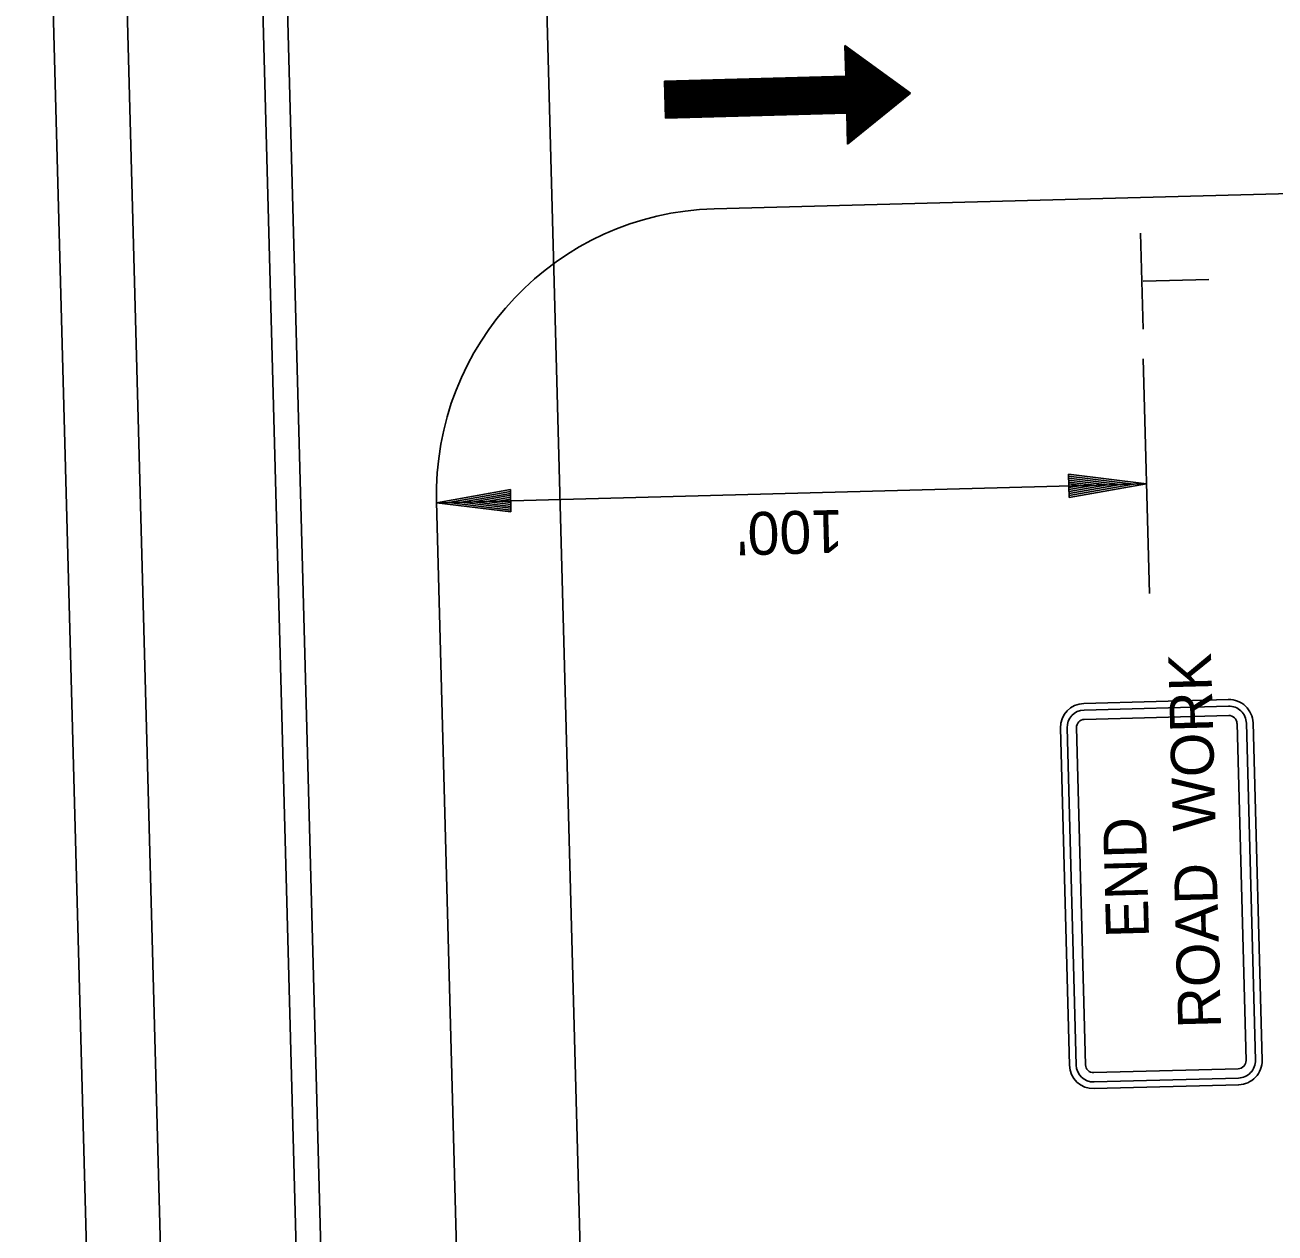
# Model space of a CAD drawing. Extents: x 1929653 to 1931621, y 596452 to 600944.
# Drawn here: x 1930900.9 to 1931163.6, y 597788.5 to 598042.4 of the extents above; entities that cross this region are included whole.
import ezdxf

# ---------------------------------------------------------------- set-up
doc = ezdxf.new("R2010")
doc.units = 0
for name, color, linetype in [('P_TC_Signs_Temporary', 7, 'Continuous'), ('R_Border', 7, 'Continuous'), ('R_Draft', 7, 'Continuous')]:
    doc.layers.add(name, color=color, linetype=linetype)

msp = doc.modelspace()

# ---------------------------------------------------------------- linework, layer by layer
at = {"layer": 'P_TC_Signs_Temporary'}
for p, q in [((1931153.84, 597900.67), (1931123.47, 597899.85)), ((1931153.87, 597899.26), (1931123.51, 597898.45)), ((1931153.93, 597897.3), (1931123.56, 597896.48)), ((1931157.56, 597824.8), (1931155.66, 597895.65)), ((1931159.53, 597824.86), (1931157.63, 597895.71)), ((1931160.93, 597824.9), (1931159.03, 597895.74)), ((1931118.55, 597894.66), (1931120.45, 597823.81)), ((1931119.95, 597894.7), (1931121.85, 597823.85)), ((1931121.92, 597894.75), (1931123.82, 597823.9)), ((1931125.55, 597822.26), (1931155.92, 597823.07)), ((1931125.61, 597820.29), (1931155.97, 597821.1)), ((1931125.65, 597818.88), (1931156.01, 597819.7))]:
    msp.add_line(p, q, dxfattribs=at)
for centre, radius, start, end in [((1931153.97, 597895.61), 5.06, 1.5377, 91.5377), ((1931123.61, 597894.79), 5.06, 91.5377, 181.5377), ((1931123.61, 597894.79), 3.66, 91.5377, 181.5377), ((1931153.97, 597895.61), 3.66, 1.5377, 91.5377), ((1931123.61, 597894.79), 1.69, 91.5377, 181.5377), ((1931153.97, 597895.61), 1.69, 1.5377, 91.5377), ((1931155.87, 597824.76), 1.69, 271.5377, 1.5377), ((1931155.87, 597824.76), 3.66, 271.5377, 1.5377), ((1931155.87, 597824.76), 5.06, 271.5377, 1.5377), ((1931125.51, 597823.94), 5.06, 181.5377, 271.5377), ((1931125.51, 597823.94), 3.66, 181.5377, 271.5377), ((1931125.51, 597823.94), 1.69, 181.5377, 271.5377)]:
    msp.add_arc(centre, radius, start, end, dxfattribs=at)
at = {"layer": 'R_Border'}
for p, q in [((1931073.28, 598038.09), (1931073.29, 598038.11)), ((1931073.28, 598037.91), (1931073.4, 598038.03)), ((1931073.29, 598037.72), (1931073.51, 598037.96)), ((1931073.29, 598037.54), (1931073.61, 598037.88)), ((1931073.3, 598037.36), (1931073.72, 598037.8)), ((1931073.3, 598037.17), (1931073.82, 598037.72)), ((1931073.31, 598036.99), (1931073.93, 598037.65)), ((1931073.31, 598036.8), (1931074.04, 598037.57)), ((1931073.32, 598036.62), (1931074.14, 598037.49)), ((1931073.32, 598036.44), (1931074.25, 598037.42)), ((1931073.33, 598036.25), (1931074.35, 598037.34)), ((1931073.33, 598036.07), (1931074.46, 598037.26)), ((1931073.34, 598035.88), (1931074.57, 598037.18)), ((1931073.34, 598035.7), (1931074.67, 598037.11)), ((1931073.34, 598035.52), (1931074.78, 598037.03)), ((1931073.35, 598035.33), (1931074.88, 598036.95)), ((1931066.05, 598023.66), (1931077.11, 598035.33)), ((1931066.23, 598023.67), (1931077.21, 598035.25)), ((1931066.42, 598023.67), (1931077.32, 598035.18)), ((1931066.6, 598023.68), (1931077.43, 598035.1)), ((1931066.78, 598023.68), (1931077.53, 598035.02)), ((1931066.97, 598023.69), (1931077.64, 598034.94)), ((1931067.15, 598023.69), (1931077.74, 598034.87)), ((1931067.34, 598023.7), (1931077.85, 598034.79)), ((1931067.52, 598023.7), (1931077.96, 598034.71)), ((1931067.7, 598023.71), (1931078.06, 598034.64)), ((1931067.89, 598023.71), (1931078.17, 598034.56)), ((1931068.07, 598023.72), (1931078.27, 598034.48)), ((1931068.25, 598023.72), (1931078.38, 598034.4)), ((1931068.44, 598023.73), (1931078.49, 598034.33)), ((1931073.35, 598035.15), (1931074.99, 598036.87)), ((1931073.36, 598034.97), (1931075.1, 598036.8)), ((1931073.36, 598034.78), (1931075.2, 598036.72)), ((1931073.37, 598034.6), (1931075.31, 598036.64)), ((1931073.37, 598034.41), (1931075.41, 598036.57)), ((1931073.38, 598034.23), (1931075.52, 598036.49)), ((1931073.38, 598034.05), (1931075.63, 598036.41)), ((1931073.39, 598033.86), (1931075.73, 598036.33)), ((1931073.39, 598033.68), (1931075.84, 598036.26)), ((1931073.4, 598033.5), (1931075.94, 598036.18)), ((1931073.4, 598033.31), (1931076.05, 598036.1)), ((1931073.41, 598033.13), (1931076.15, 598036.03)), ((1931073.41, 598032.94), (1931076.26, 598035.95)), ((1931073.42, 598032.76), (1931076.37, 598035.87)), ((1931073.42, 598032.58), (1931076.47, 598035.79)), ((1931073.43, 598032.39), (1931076.58, 598035.72)), ((1931073.43, 598032.21), (1931076.68, 598035.64)), ((1931073.44, 598032.03), (1931076.79, 598035.56)), ((1931073.44, 598031.84), (1931076.9, 598035.49)), ((1931073.45, 598031.66), (1931077, 598035.41)), ((1931065.31, 598023.64), (1931072.88, 598031.63)), ((1931065.5, 598023.65), (1931073.07, 598031.63)), ((1931065.68, 598023.65), (1931073.25, 598031.64)), ((1931065.87, 598023.66), (1931073.43, 598031.64)), ((1931068.62, 598023.73), (1931078.59, 598034.25)), ((1931068.81, 598023.74), (1931078.7, 598034.17)), ((1931068.99, 598023.74), (1931078.8, 598034.1)), ((1931069.17, 598023.75), (1931078.91, 598034.02)), ((1931069.36, 598023.75), (1931079.02, 598033.94)), ((1931069.54, 598023.76), (1931079.12, 598033.86)), ((1931069.72, 598023.76), (1931079.23, 598033.79)), ((1931069.91, 598023.77), (1931079.33, 598033.71)), ((1931070.09, 598023.77), (1931079.44, 598033.63)), ((1931070.28, 598023.78), (1931079.55, 598033.56)), ((1931070.46, 598023.78), (1931079.65, 598033.48)), ((1931070.64, 598023.78), (1931079.76, 598033.4)), ((1931070.83, 598023.79), (1931079.86, 598033.32)), ((1931071.01, 598023.79), (1931079.97, 598033.25)), ((1931071.2, 598023.8), (1931080.07, 598033.17)), ((1931071.38, 598023.8), (1931080.18, 598033.09)), ((1931071.56, 598023.81), (1931080.29, 598033.01)), ((1931071.75, 598023.81), (1931080.39, 598032.94)), ((1931071.93, 598023.82), (1931080.5, 598032.86)), ((1931072.11, 598023.82), (1931080.6, 598032.78)), ((1931072.3, 598023.83), (1931080.71, 598032.71)), ((1931072.48, 598023.83), (1931080.82, 598032.63)), ((1931072.67, 598023.84), (1931080.92, 598032.55)), ((1931072.85, 598023.84), (1931081.03, 598032.47)), ((1931073.03, 598023.85), (1931081.13, 598032.4)), ((1931073.22, 598023.85), (1931081.24, 598032.32)), ((1931073.4, 598023.86), (1931081.35, 598032.24)), ((1931073.58, 598023.86), (1931081.45, 598032.17)), ((1931073.66, 598023.76), (1931081.56, 598032.09)), ((1931073.67, 598023.57), (1931081.66, 598032.01)), ((1931073.67, 598023.39), (1931081.77, 598031.93)), ((1931073.68, 598023.2), (1931081.88, 598031.86)), ((1931073.68, 598023.02), (1931081.98, 598031.78)), ((1931073.69, 598022.84), (1931082.09, 598031.7)), ((1931035.31, 598030.54), (1931035.39, 598030.62)), ((1931035.32, 598030.17), (1931035.76, 598030.63)), ((1931035.32, 598030.36), (1931035.57, 598030.63)), ((1931035.33, 598029.8), (1931036.13, 598030.64)), ((1931035.33, 598029.99), (1931035.94, 598030.64)), ((1931035.34, 598029.44), (1931036.49, 598030.65)), ((1931035.34, 598029.62), (1931036.31, 598030.65)), ((1931035.35, 598029.07), (1931036.86, 598030.66)), ((1931035.35, 598029.25), (1931036.68, 598030.66)), ((1931035.36, 598028.7), (1931037.23, 598030.67)), ((1931035.36, 598028.89), (1931037.05, 598030.67)), ((1931035.37, 598028.33), (1931037.6, 598030.68)), ((1931035.37, 598028.52), (1931037.41, 598030.68)), ((1931035.38, 598027.97), (1931037.96, 598030.69)), ((1931035.38, 598028.15), (1931037.78, 598030.69)), ((1931035.39, 598027.6), (1931038.33, 598030.7)), ((1931035.39, 598027.78), (1931038.15, 598030.7)), ((1931035.4, 598027.23), (1931038.7, 598030.71)), ((1931035.4, 598027.41), (1931038.52, 598030.71)), ((1931035.41, 598026.86), (1931039.07, 598030.72)), ((1931035.41, 598027.05), (1931038.88, 598030.72)), ((1931035.42, 598026.5), (1931039.43, 598030.73)), ((1931035.42, 598026.68), (1931039.25, 598030.72)), ((1931035.43, 598026.13), (1931039.8, 598030.74)), ((1931035.43, 598026.31), (1931039.62, 598030.73)), ((1931035.44, 598025.76), (1931040.17, 598030.75)), ((1931035.44, 598025.94), (1931039.99, 598030.74)), ((1931035.45, 598025.39), (1931040.54, 598030.76)), ((1931035.45, 598025.58), (1931040.35, 598030.75)), ((1931035.46, 598025.03), (1931040.9, 598030.77)), ((1931035.46, 598025.21), (1931040.72, 598030.76)), ((1931035.47, 598024.66), (1931041.27, 598030.78)), ((1931035.47, 598024.84), (1931041.09, 598030.77)), ((1931035.48, 598024.29), (1931041.64, 598030.79)), ((1931035.48, 598024.47), (1931041.46, 598030.78)), ((1931035.49, 598023.92), (1931042.01, 598030.8)), ((1931035.49, 598024.11), (1931041.82, 598030.79)), ((1931035.5, 598023.56), (1931042.37, 598030.81)), ((1931035.5, 598023.74), (1931042.19, 598030.8)), ((1931035.51, 598023.19), (1931042.74, 598030.82)), ((1931035.51, 598023.37), (1931042.56, 598030.81)), ((1931035.52, 598023), (1931042.93, 598030.82)), ((1931035.54, 598022.84), (1931043.11, 598030.83)), ((1931035.73, 598022.85), (1931043.29, 598030.83)), ((1931035.91, 598022.85), (1931043.48, 598030.84)), ((1931036.09, 598022.86), (1931043.66, 598030.84)), ((1931036.28, 598022.86), (1931043.85, 598030.85)), ((1931036.46, 598022.87), (1931044.03, 598030.85)), ((1931036.64, 598022.87), (1931044.21, 598030.86)), ((1931036.83, 598022.88), (1931044.4, 598030.86)), ((1931037.01, 598022.88), (1931044.58, 598030.87)), ((1931037.2, 598022.89), (1931044.76, 598030.87)), ((1931037.38, 598022.89), (1931044.95, 598030.88)), ((1931037.56, 598022.9), (1931045.13, 598030.88)), ((1931037.75, 598022.9), (1931045.32, 598030.89)), ((1931037.93, 598022.91), (1931045.5, 598030.89)), ((1931038.11, 598022.91), (1931045.68, 598030.9)), ((1931038.3, 598022.92), (1931045.87, 598030.9)), ((1931038.48, 598022.92), (1931046.05, 598030.91)), ((1931038.67, 598022.93), (1931046.23, 598030.91)), ((1931038.85, 598022.93), (1931046.42, 598030.92)), ((1931039.03, 598022.94), (1931046.6, 598030.92)), ((1931039.22, 598022.94), (1931046.79, 598030.93)), ((1931039.4, 598022.95), (1931046.97, 598030.93)), ((1931039.58, 598022.95), (1931047.15, 598030.94)), ((1931039.77, 598022.96), (1931047.34, 598030.94)), ((1931039.95, 598022.96), (1931047.52, 598030.95)), ((1931040.14, 598022.97), (1931047.7, 598030.95)), ((1931040.32, 598022.97), (1931047.89, 598030.96)), ((1931040.5, 598022.98), (1931048.07, 598030.96)), ((1931040.69, 598022.98), (1931048.26, 598030.97)), ((1931040.87, 598022.99), (1931048.44, 598030.97)), ((1931041.05, 598022.99), (1931048.62, 598030.98)), ((1931041.24, 598023), (1931048.81, 598030.98)), ((1931041.42, 598023), (1931048.99, 598030.99)), ((1931041.61, 598023.01), (1931049.17, 598030.99)), ((1931041.79, 598023.01), (1931049.36, 598031)), ((1931041.97, 598023.02), (1931049.54, 598031)), ((1931042.16, 598023.02), (1931049.73, 598031.01)), ((1931042.34, 598023.03), (1931049.91, 598031.01)), ((1931042.53, 598023.03), (1931050.09, 598031.02)), ((1931042.71, 598023.03), (1931050.28, 598031.02)), ((1931042.89, 598023.04), (1931050.46, 598031.03)), ((1931043.08, 598023.04), (1931050.64, 598031.03)), ((1931043.26, 598023.05), (1931050.83, 598031.04)), ((1931043.44, 598023.05), (1931051.01, 598031.04)), ((1931043.63, 598023.06), (1931051.2, 598031.05)), ((1931043.81, 598023.06), (1931051.38, 598031.05)), ((1931044, 598023.07), (1931051.56, 598031.06)), ((1931044.18, 598023.07), (1931051.75, 598031.06)), ((1931044.36, 598023.08), (1931051.93, 598031.07)), ((1931044.55, 598023.08), (1931052.12, 598031.07)), ((1931044.73, 598023.09), (1931052.3, 598031.08)), ((1931044.91, 598023.09), (1931052.48, 598031.08)), ((1931045.1, 598023.1), (1931052.67, 598031.09)), ((1931045.28, 598023.1), (1931052.85, 598031.09)), ((1931045.47, 598023.11), (1931053.03, 598031.09)), ((1931045.65, 598023.11), (1931053.22, 598031.1)), ((1931045.83, 598023.12), (1931053.4, 598031.1)), ((1931046.02, 598023.12), (1931053.59, 598031.11)), ((1931046.2, 598023.13), (1931053.77, 598031.11)), ((1931046.38, 598023.13), (1931053.95, 598031.12)), ((1931046.57, 598023.14), (1931054.14, 598031.12)), ((1931046.75, 598023.14), (1931054.32, 598031.13)), ((1931046.94, 598023.15), (1931054.5, 598031.13)), ((1931047.12, 598023.15), (1931054.69, 598031.14)), ((1931047.3, 598023.16), (1931054.87, 598031.14)), ((1931047.49, 598023.16), (1931055.06, 598031.15)), ((1931047.67, 598023.17), (1931055.24, 598031.15)), ((1931047.85, 598023.17), (1931055.42, 598031.16)), ((1931048.04, 598023.18), (1931055.61, 598031.16)), ((1931048.22, 598023.18), (1931055.79, 598031.17)), ((1931048.41, 598023.19), (1931055.97, 598031.17)), ((1931048.59, 598023.19), (1931056.16, 598031.18)), ((1931048.77, 598023.2), (1931056.34, 598031.18)), ((1931048.96, 598023.2), (1931056.53, 598031.19)), ((1931049.14, 598023.21), (1931056.71, 598031.19)), ((1931049.33, 598023.21), (1931056.89, 598031.2)), ((1931049.51, 598023.22), (1931057.08, 598031.2)), ((1931049.69, 598023.22), (1931057.26, 598031.21)), ((1931049.88, 598023.23), (1931057.44, 598031.21)), ((1931050.06, 598023.23), (1931057.63, 598031.22)), ((1931050.24, 598023.24), (1931057.81, 598031.22)), ((1931050.43, 598023.24), (1931058, 598031.23)), ((1931050.61, 598023.25), (1931058.18, 598031.23)), ((1931050.8, 598023.25), (1931058.36, 598031.24)), ((1931050.98, 598023.26), (1931058.55, 598031.24)), ((1931051.16, 598023.26), (1931058.73, 598031.25)), ((1931051.35, 598023.27), (1931058.92, 598031.25)), ((1931051.53, 598023.27), (1931059.1, 598031.26)), ((1931051.71, 598023.28), (1931059.28, 598031.26)), ((1931051.9, 598023.28), (1931059.47, 598031.27)), ((1931052.08, 598023.29), (1931059.65, 598031.27)), ((1931052.27, 598023.29), (1931059.83, 598031.28)), ((1931052.45, 598023.3), (1931060.02, 598031.28)), ((1931052.63, 598023.3), (1931060.2, 598031.29)), ((1931052.82, 598023.31), (1931060.39, 598031.29)), ((1931053, 598023.31), (1931060.57, 598031.3)), ((1931053.18, 598023.32), (1931060.75, 598031.3)), ((1931053.37, 598023.32), (1931060.94, 598031.31)), ((1931053.55, 598023.33), (1931061.12, 598031.31)), ((1931053.74, 598023.33), (1931061.3, 598031.32)), ((1931053.92, 598023.34), (1931061.49, 598031.32)), ((1931054.1, 598023.34), (1931061.67, 598031.33)), ((1931054.29, 598023.35), (1931061.86, 598031.33)), ((1931054.47, 598023.35), (1931062.04, 598031.34)), ((1931054.65, 598023.36), (1931062.22, 598031.34)), ((1931054.84, 598023.36), (1931062.41, 598031.35)), ((1931055.02, 598023.37), (1931062.59, 598031.35)), ((1931055.21, 598023.37), (1931062.77, 598031.36)), ((1931055.39, 598023.38), (1931062.96, 598031.36)), ((1931055.57, 598023.38), (1931063.14, 598031.37)), ((1931055.76, 598023.39), (1931063.33, 598031.37)), ((1931055.94, 598023.39), (1931063.51, 598031.38)), ((1931056.12, 598023.4), (1931063.69, 598031.38)), ((1931056.31, 598023.4), (1931063.88, 598031.39)), ((1931056.49, 598023.4), (1931064.06, 598031.39)), ((1931056.68, 598023.41), (1931064.24, 598031.4)), ((1931056.86, 598023.41), (1931064.43, 598031.4)), ((1931057.04, 598023.42), (1931064.61, 598031.41)), ((1931057.23, 598023.42), (1931064.8, 598031.41)), ((1931057.41, 598023.43), (1931064.98, 598031.42)), ((1931057.6, 598023.43), (1931065.16, 598031.42)), ((1931057.78, 598023.44), (1931065.35, 598031.43)), ((1931057.96, 598023.44), (1931065.53, 598031.43)), ((1931058.15, 598023.45), (1931065.72, 598031.44)), ((1931058.33, 598023.45), (1931065.9, 598031.44)), ((1931058.51, 598023.46), (1931066.08, 598031.45)), ((1931058.7, 598023.46), (1931066.27, 598031.45)), ((1931058.88, 598023.47), (1931066.45, 598031.46)), ((1931059.07, 598023.47), (1931066.63, 598031.46)), ((1931059.25, 598023.48), (1931066.82, 598031.46)), ((1931059.43, 598023.48), (1931067, 598031.47)), ((1931059.62, 598023.49), (1931067.19, 598031.47)), ((1931059.8, 598023.49), (1931067.37, 598031.48)), ((1931059.98, 598023.5), (1931067.55, 598031.48)), ((1931060.17, 598023.5), (1931067.74, 598031.49)), ((1931060.35, 598023.51), (1931067.92, 598031.49)), ((1931060.54, 598023.51), (1931068.1, 598031.5)), ((1931060.72, 598023.52), (1931068.29, 598031.5)), ((1931060.9, 598023.52), (1931068.47, 598031.51)), ((1931061.09, 598023.53), (1931068.66, 598031.51)), ((1931061.27, 598023.53), (1931068.84, 598031.52)), ((1931061.45, 598023.54), (1931069.02, 598031.52)), ((1931061.64, 598023.54), (1931069.21, 598031.53)), ((1931061.82, 598023.55), (1931069.39, 598031.53)), ((1931062.01, 598023.55), (1931069.57, 598031.54)), ((1931062.19, 598023.56), (1931069.76, 598031.54)), ((1931062.37, 598023.56), (1931069.94, 598031.55)), ((1931062.56, 598023.57), (1931070.13, 598031.55)), ((1931062.74, 598023.57), (1931070.31, 598031.56)), ((1931062.92, 598023.58), (1931070.49, 598031.56)), ((1931063.11, 598023.58), (1931070.68, 598031.57)), ((1931063.29, 598023.59), (1931070.86, 598031.57)), ((1931063.48, 598023.59), (1931071.04, 598031.58)), ((1931063.66, 598023.6), (1931071.23, 598031.58)), ((1931063.84, 598023.6), (1931071.41, 598031.59)), ((1931064.03, 598023.61), (1931071.6, 598031.59)), ((1931064.21, 598023.61), (1931071.78, 598031.6)), ((1931064.4, 598023.62), (1931071.96, 598031.6)), ((1931064.58, 598023.62), (1931072.15, 598031.61)), ((1931064.76, 598023.63), (1931072.33, 598031.61)), ((1931064.95, 598023.63), (1931072.51, 598031.62)), ((1931065.13, 598023.64), (1931072.7, 598031.62)), ((1931073.69, 598022.65), (1931082.19, 598031.63)), ((1931073.7, 598022.47), (1931082.3, 598031.55)), ((1931073.7, 598022.29), (1931082.41, 598031.47)), ((1931073.71, 598022.1), (1931082.51, 598031.39)), ((1931073.71, 598021.92), (1931082.62, 598031.32)), ((1931073.71, 598021.73), (1931082.72, 598031.24)), ((1931073.72, 598021.55), (1931082.83, 598031.16)), ((1931073.72, 598021.37), (1931082.94, 598031.08)), ((1931073.73, 598021.18), (1931083.04, 598031.01)), ((1931073.73, 598021), (1931083.15, 598030.93)), ((1931073.74, 598020.81), (1931083.25, 598030.85)), ((1931073.74, 598020.63), (1931083.36, 598030.78)), ((1931073.75, 598020.45), (1931083.46, 598030.7)), ((1931073.75, 598020.26), (1931083.57, 598030.62)), ((1931073.76, 598020.08), (1931083.68, 598030.54)), ((1931073.76, 598019.9), (1931083.78, 598030.47)), ((1931073.77, 598019.71), (1931083.89, 598030.39)), ((1931073.77, 598019.53), (1931083.99, 598030.31)), ((1931073.78, 598019.34), (1931084.1, 598030.24)), ((1931073.78, 598019.16), (1931084.21, 598030.16)), ((1931073.79, 598018.98), (1931084.31, 598030.08)), ((1931073.79, 598018.79), (1931084.42, 598030)), ((1931073.8, 598018.61), (1931084.52, 598029.93)), ((1931073.8, 598018.43), (1931084.63, 598029.85)), ((1931073.81, 598018.24), (1931084.74, 598029.77)), ((1931073.81, 598018.06), (1931084.84, 598029.7)), ((1931073.82, 598017.87), (1931084.95, 598029.62)), ((1931073.82, 598017.69), (1931085.05, 598029.54)), ((1931073.83, 598017.51), (1931085.16, 598029.46)), ((1931074.1, 598017.6), (1931085.27, 598029.39)), ((1931074.88, 598018.24), (1931085.37, 598029.31)), ((1931075.66, 598018.88), (1931085.48, 598029.23)), ((1931076.45, 598019.52), (1931085.58, 598029.15)), ((1931077.23, 598020.15), (1931085.69, 598029.08)), ((1931078.02, 598020.79), (1931085.8, 598029)), ((1931078.8, 598021.43), (1931085.9, 598028.92)), ((1931079.59, 598022.07), (1931086.01, 598028.85)), ((1931080.37, 598022.71), (1931086.11, 598028.77)), ((1931081.16, 598023.35), (1931086.22, 598028.69)), ((1931081.94, 598023.99), (1931086.33, 598028.61)), ((1931082.72, 598024.63), (1931086.43, 598028.54)), ((1931083.51, 598025.26), (1931086.54, 598028.46)), ((1931084.29, 598025.9), (1931086.64, 598028.38)), ((1931085.08, 598026.54), (1931086.75, 598028.31)), ((1931085.86, 598027.18), (1931086.86, 598028.23)), ((1931086.65, 598027.82), (1931086.96, 598028.15))]:
    msp.add_line(p, q, dxfattribs=at)
at = {"layer": 'R_Draft'}
for p, q in [((1931004.63, 598268.26), (1931029.13, 597355.62)), ((1930900.94, 598265.48), (1930925.44, 597352.83)), ((1930916.49, 598265.9), (1930935.8, 597546.71)), ((1930945, 598266.66), (1930969.5, 597354.02)), ((1930950.2, 598266.8), (1930974.7, 597354.16)), ((1931073.27, 598038.12), (1931073.45, 598031.64)), ((1931073.27, 598038.12), (1931087.01, 598028.12)), ((1931073.45, 598031.64), (1931035.31, 598030.62)), ((1931035.31, 598030.62), (1931035.52, 598022.84)), ((1931087.01, 598028.12), (1931073.83, 598017.38)), ((1931073.66, 598023.87), (1931035.52, 598022.84)), ((1931073.66, 598023.87), (1931073.83, 598017.38)), ((1931207.9, 598008.14), (1931045.81, 598003.78)), ((1931135.94, 597978.51), (1931135.4, 597998.7)), ((1931135.97, 597988.57), (1931149.75, 597988.94)), ((1931137.26, 597922.94), (1931135.94, 597972.26)), ((1931120.26, 597948.03), (1931136.64, 597946.02)), ((1931120.26, 597948.03), (1931120.39, 597943.13)), ((1931120.27, 597947.63), (1931133.91, 597945.94)), ((1930987.43, 597942.01), (1931136.64, 597946.02)), ((1931120.29, 597947.2), (1931131.11, 597945.87)), ((1931120.3, 597946.8), (1931128.39, 597945.79)), ((1931120.31, 597946.37), (1931125.63, 597945.72)), ((1931120.31, 597945.97), (1931122.9, 597945.65)), ((1931120.33, 597945.2), (1931122.9, 597945.65)), ((1931120.35, 597944.78), (1931125.63, 597945.72)), ((1931120.36, 597944.37), (1931128.39, 597945.79)), ((1931120.37, 597943.96), (1931131.11, 597945.87)), ((1931120.38, 597943.55), (1931133.91, 597945.94)), ((1931120.39, 597943.13), (1931136.64, 597946.02)), ((1931002.95, 597944.77), (1930987.39, 597942.01)), ((1931002.96, 597944.38), (1930990, 597942.08)), ((1931002.97, 597943.98), (1930992.69, 597942.15)), ((1931002.98, 597943.59), (1930995.29, 597942.22)), ((1931002.99, 597943.19), (1930997.94, 597942.29)), ((1931003, 597942.79), (1931000.55, 597942.36)), ((1931003.02, 597942.06), (1931000.55, 597942.36)), ((1931003.07, 597940.09), (1931002.95, 597944.77)), ((1931003.07, 597940.09), (1930987.39, 597942.01)), ((1930987.44, 597942.2), (1931003.21, 597354.92)), ((1931003.06, 597940.47), (1930990, 597942.08)), ((1931003.05, 597940.87), (1930992.69, 597942.15)), ((1931003.04, 597941.26), (1930995.29, 597942.22)), ((1931003.03, 597941.67), (1930997.94, 597942.29))]:
    msp.add_line(p, q, dxfattribs=at)
msp.add_arc((1931047.42, 597943.81), 60, 91.5377, 181.5377, dxfattribs=at)

# ---------------------------------------------------------------- texts
at = {"layer": 'P_TC_Signs_Temporary'}
for s, p in [('ROAD  WORK', (1931152.31, 597831.66)), ('END', (1931137.17, 597850.66))]:
    msp.add_text(s, height=9, rotation=91.5377, dxfattribs=at).set_placement(p)
at = {"layer": 'R_Border'}
msp.add_text("100'", height=9, rotation=181.5377, dxfattribs=at).set_placement((1931072.75, 597940.55))

doc.saveas('drawing.dxf')
